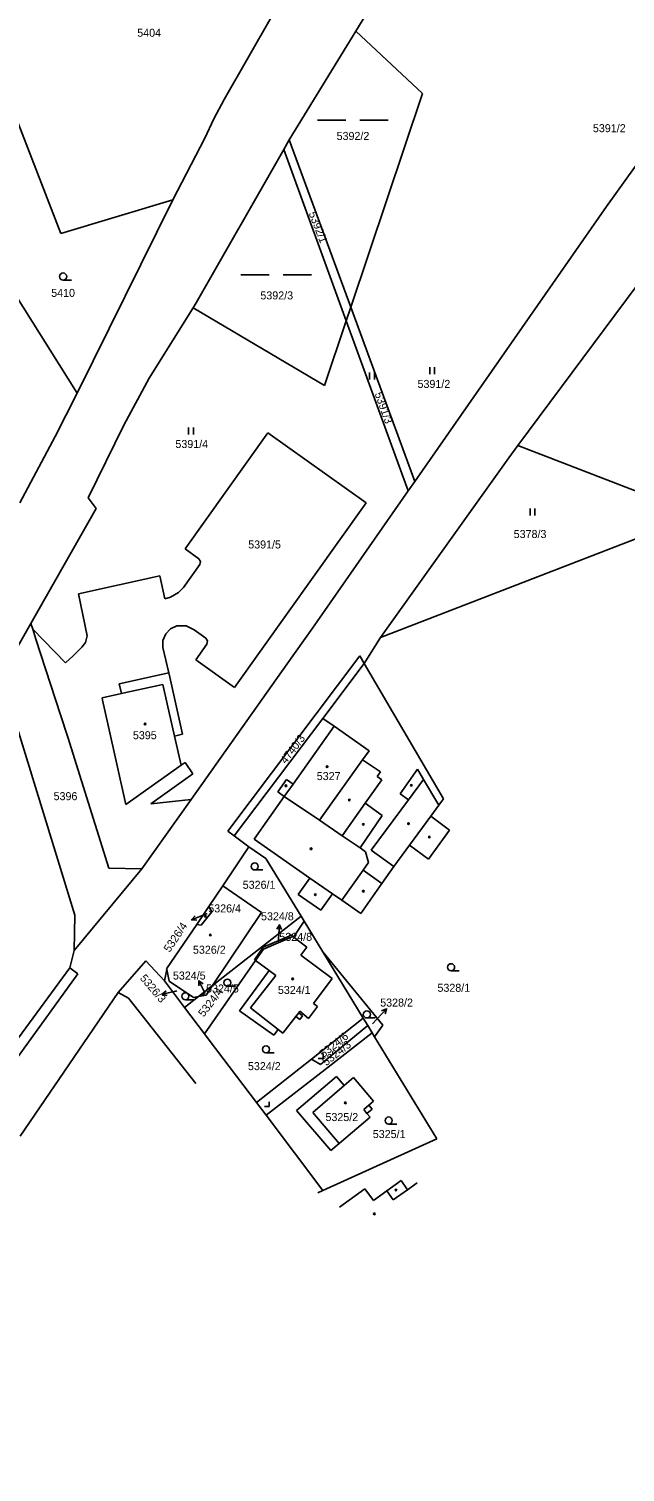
# Model space of a CAD drawing. Extents: x -717507 to -715515, y -957700 to -954941.
# Drawn here: x -716103.3 to -715976.7, y -955758.9 to -955452.3 of the extents above; entities that cross this region are included whole.
import ezdxf

# ---------------------------------------------------------------- set-up
doc = ezdxf.new("R2010")
doc.units = 0
for name, color, linetype in [('Hranice parcel', 7, 'Continuous'), ('Parcelní čísla', 7, 'Continuous'), ('Pop  PČ popisy', 7, 'Continuous'), ('Vnitřní kresba', 7, 'Continuous'), ('Značky budov', 7, 'Continuous'), ('Značky kultur', 7, 'Continuous')]:
    doc.layers.add(name, color=color, linetype=linetype)

msp = doc.modelspace()

# ---------------------------------------------------------------- linework, layer by layer
at = {"layer": 'Hranice parcel'}
for points in [[(-715980.61, -955490.06), (-715936.99, -955429.22)], [(-716033.91, -955452.78), (-716027.09, -955441.61)], [(-716061.85, -955467.33), (-716051.78, -955449.79)], [(-716048.01, -955475.9), (-716033.91, -955452.78)], [(-716033.91, -955452.78), (-716019.74, -955466.03)], [(-716064.05, -955471.46), (-716061.85, -955467.33)], [(-716034.97, -955511.43), (-716019.74, -955466.03)], [(-716106.79, -955469.23), (-716096.54, -955495.81)], [(-716065.97, -955475.56), (-716064.05, -955471.46)], [(-716072.73, -955488.62), (-716065.97, -955475.56)], [(-716049.2, -955477.98), (-716048.01, -955475.9)], [(-716048.01, -955475.9), (-716034.97, -955511.43)], [(-716067.78, -955510.54), (-716049.2, -955477.98)], [(-716049.2, -955477.98), (-716035.94, -955514.32)], [(-716096.54, -955495.81), (-716072.73, -955488.62)], [(-716093.1, -955529.72), (-716072.73, -955488.62)], [(-716021.37, -955548.49), (-715980.61, -955490.06)], [(-715999.46, -955540.82), (-715969.56, -955500.7)], [(-716106.5, -955508.39), (-716093.1, -955529.72)], [(-716068.43, -955511.57), (-716067.78, -955510.54)], [(-716077.82, -955526.49), (-716068.43, -955511.57)], [(-716068.43, -955511.57), (-716040.55, -955528.07)], [(-716035.94, -955514.32), (-716034.97, -955511.43)], [(-716034.97, -955511.43), (-716021.37, -955548.49)], [(-716040.55, -955528.07), (-716035.94, -955514.32)], [(-716035.94, -955514.32), (-716022.75, -955550.46)], [(-716083.19, -955536.49), (-716077.82, -955526.49)], [(-716097.74, -955538.89), (-716093.1, -955529.72)], [(-716090.76, -955551.92), (-716083.19, -955536.49)], [(-716070.13, -955562.79), (-716052.56, -955538.14)], [(-716052.56, -955538.14), (-716031.66, -955552.99)], [(-716105.29, -955552.97), (-716097.74, -955538.89)], [(-716001.39, -955543.41), (-715999.46, -955540.82)], [(-715999.46, -955540.82), (-715961.64, -955555.4)], [(-716028.66, -955581.62), (-716001.39, -955543.41)], [(-716042.11, -955578.21), (-716022.75, -955550.46)], [(-716022.75, -955550.46), (-716021.37, -955548.49)], [(-716090.76, -955551.92), (-716089.04, -955554.17)], [(-716031.66, -955552.99), (-716059.64, -955592.22)], [(-716102.92, -955578.62), (-716089.04, -955554.17)], [(-716028.66, -955581.62), (-715967.26, -955557.9)], [(-716067.22, -955564.87), (-716070.13, -955562.79)], [(-716070.52, -955571.02), (-716067.02, -955566.13)], [(-716066.85, -955565.46), (-716067.22, -955564.87)], [(-716067.02, -955566.13), (-716066.85, -955565.46)], [(-716092.79, -955572.36), (-716075.5, -955568.52)], [(-716075.5, -955568.52), (-716074.47, -955573.38)], [(-716073.24, -955573.07), (-716071.53, -955572.08)], [(-716071.53, -955572.08), (-716070.52, -955571.02)], [(-716090.94, -955581.22), (-716092.79, -955572.36)], [(-716074.47, -955573.38), (-716073.24, -955573.07)], [(-716043.08, -955579.59), (-716042.11, -955578.21)], [(-716109.23, -955589.72), (-716102.92, -955578.62)], [(-716102.53, -955579.81), (-716102.92, -955578.62)], [(-716102.53, -955579.81), (-716095.55, -955587.02)], [(-716101.83, -955581.98), (-716102.53, -955579.81)], [(-716091.29, -955582.68), (-716090.94, -955581.22)], [(-716074.26, -955580.84), (-716074.86, -955582.23)], [(-716073.23, -955579.76), (-716074.26, -955580.84)], [(-716071.9, -955579.14), (-716073.23, -955579.76)], [(-716069.94, -955579.11), (-716071.9, -955579.14)], [(-716068.21, -955579.99), (-716069.94, -955579.11)], [(-716065.76, -955581.72), (-716068.21, -955579.99)], [(-716048.45, -955587.22), (-716043.08, -955579.59)], [(-716101.83, -955581.98), (-716096.62, -955598)], [(-716093.95, -955585.52), (-716092.06, -955583.68)], [(-716092.06, -955583.68), (-716091.29, -955582.68)], [(-716074.86, -955582.23), (-716074.89, -955583.73)], [(-716074.89, -955583.73), (-716073.62, -955589.09)], [(-716067.9, -955586.32), (-716065.54, -955583)], [(-716065.39, -955582.31), (-716065.76, -955581.72)], [(-716065.54, -955583), (-716065.39, -955582.31)], [(-716032.08, -955587.12), (-716028.66, -955581.62)], [(-716095.55, -955587.02), (-716093.95, -955585.52)], [(-716068.85, -955615.99), (-716048.45, -955587.22)], [(-716059.64, -955592.22), (-716067.9, -955586.32)], [(-716061.05, -955622.71), (-716033.01, -955585.53)], [(-716040.92, -955598.84), (-716032.08, -955587.12)], [(-716033.01, -955585.53), (-716032.08, -955587.12)], [(-716032.08, -955587.12), (-716015.28, -955615.88)], [(-716084.16, -955591.46), (-716073.62, -955589.09)], [(-716073.62, -955589.09), (-716073.41, -955590.02)], [(-716073.41, -955590.02), (-716072.25, -955595.15)], [(-716108.34, -955592.62), (-716093.6, -955640.58)], [(-716087.79, -955594.43), (-716083.69, -955593.52)], [(-716083.69, -955593.52), (-716084.16, -955591.46)], [(-716087.68, -955594.93), (-716087.79, -955594.43)], [(-716086.57, -955599.93), (-716087.68, -955594.93)], [(-716072.25, -955595.15), (-716070.68, -955602.15)], [(-716096.62, -955598), (-716095.07, -955602.76)], [(-716059.7, -955623.74), (-716040.92, -955598.84)], [(-716040.92, -955598.84), (-716038.5, -955600.47)], [(-716095.07, -955602.76), (-716086.37, -955630.6)], [(-716082.76, -955617.05), (-716086.57, -955599.93)], [(-716070.68, -955602.15), (-716072.41, -955602.58)], [(-716072.41, -955602.58), (-716071.02, -955608.74)], [(-716047.22, -955612.76), (-716038.5, -955600.47)], [(-716071.02, -955608.74), (-716082.76, -955617.05)], [(-716071.02, -955608.74), (-716070.13, -955608.17)], [(-716070.13, -955608.17), (-716068.5, -955610.53)], [(-716068.5, -955610.53), (-716077.44, -955616.92)], [(-716050.47, -955614.38), (-716048.61, -955611.77)], [(-716048.61, -955611.77), (-716047.22, -955612.76)], [(-716050.47, -955614.38), (-716049.07, -955615.37)], [(-716079.31, -955630.74), (-716068.85, -955615.99)], [(-716077.44, -955616.92), (-716068.85, -955615.99)], [(-716055.51, -955624.44), (-716049.07, -955615.37)], [(-716017.96, -955619.55), (-716016.24, -955617.2)], [(-716016.24, -955617.2), (-716015.28, -955615.88)], [(-716017.96, -955619.55), (-716013.99, -955622.56)], [(-716059.7, -955623.74), (-716061.05, -955622.71)], [(-716059.7, -955623.74), (-716056.62, -955626.1)], [(-716018.41, -955628.66), (-716013.99, -955622.56)], [(-716062.16, -955634.37), (-716056.62, -955626.1)], [(-716056.62, -955626.1), (-716052.98, -955628.58)], [(-716055.51, -955624.44), (-716043.66, -955632.69)], [(-716025.79, -955630.27), (-716022.45, -955625.71)], [(-716022.45, -955625.71), (-716018.41, -955628.66)], [(-716052.98, -955628.58), (-716045.51, -955640.82)], [(-716028.32, -955633.85), (-716025.79, -955630.27)], [(-716093.74, -955648.11), (-716079.31, -955630.74)], [(-716086.37, -955630.6), (-716079.31, -955630.74)], [(-716046.12, -955636.22), (-716043.66, -955632.69)], [(-716065.11, -955638.74), (-716062.16, -955634.37)], [(-716062.16, -955634.37), (-716053.91, -955640.05)], [(-716046.12, -955636.22), (-716041.28, -955639.53)], [(-716041.28, -955639.53), (-716038.84, -955636.05)], [(-716038.84, -955636.05), (-716036.87, -955637.43)], [(-716032.85, -955640.23), (-716028.32, -955633.85)], [(-716067.69, -955642.55), (-716065.11, -955638.74)], [(-716065.11, -955638.74), (-716064.48, -955639.88)], [(-716036.87, -955637.43), (-716032.85, -955640.23)], [(-716093.74, -955648.11), (-716093.6, -955640.58)], [(-716074.07, -955651.99), (-716067.69, -955642.55)], [(-716067.69, -955642.55), (-716066.74, -955642.72)], [(-716066.74, -955642.72), (-716064.48, -955639.88)], [(-716064.34, -955655.54), (-716053.91, -955640.05)], [(-716064.34, -955655.54), (-716045.51, -955640.82)], [(-716046.97, -955645.01), (-716044.88, -955641.85)], [(-716045.51, -955640.82), (-716044.88, -955641.85)], [(-716044.88, -955641.85), (-716040.9, -955648.37)], [(-716053.55, -955647.39), (-716048.03, -955645.01)], [(-716047.23, -955645.12), (-716053.52, -955647.84)], [(-716048.03, -955645.01), (-716047.79, -955644.69)], [(-716047.79, -955644.69), (-716047.23, -955645.12)], [(-716046.97, -955645.01), (-716047.23, -955645.12)], [(-716047.23, -955645.12), (-716044.32, -955647.36)], [(-716094.64, -955651.79), (-716093.74, -955648.11)], [(-716055.42, -955650.07), (-716053.55, -955647.39)], [(-716053.52, -955647.84), (-716055.19, -955650.24)], [(-716044.32, -955647.36), (-716045.56, -955649.07)], [(-716040.9, -955648.37), (-716028.12, -955663.97)], [(-716040.9, -955648.37), (-716032.29, -955662.48)], [(-716133.06, -955704.12), (-716094.64, -955651.79)], [(-716084.35, -955657.02), (-716078.47, -955650.31)], [(-716078.47, -955650.31), (-716074.53, -955654.55)], [(-716074.07, -955651.99), (-716074.04, -955652.15)], [(-716055.19, -955650.24), (-716066.02, -955665.8)], [(-716055.19, -955650.24), (-716055.42, -955650.07)], [(-716052.3, -955652.37), (-716055.19, -955650.24)], [(-716045.56, -955649.07), (-716038.9, -955654.06)], [(-716074.53, -955654.55), (-716074.04, -955652.15)], [(-716074.53, -955654.55), (-716070.28, -955660.17)], [(-716074.04, -955652.15), (-716073.52, -955654.59)], [(-716073.52, -955654.59), (-716068.37, -955658.06)], [(-716058.58, -955660.88), (-716052.3, -955652.37)], [(-716042.86, -955659.34), (-716038.9, -955654.06)], [(-716105.18, -955687.56), (-716084.35, -955657.02)], [(-716084.35, -955657.02), (-716082.21, -955658.24)], [(-716070.28, -955660.17), (-716067.33, -955657.87)], [(-716068.37, -955658.06), (-716067.33, -955657.87)], [(-716067.33, -955657.87), (-716064.34, -955655.54)], [(-716067.33, -955657.87), (-716065.71, -955657.57)], [(-716065.71, -955657.57), (-716064.34, -955655.54)], [(-716082.21, -955658.24), (-716067.89, -955676.36)], [(-716070.28, -955660.17), (-716066.02, -955665.8)], [(-716058.58, -955660.88), (-716051.32, -955666.06)], [(-716046.02, -955661.32), (-716045.77, -955661.01)], [(-716045.77, -955661.01), (-716043.91, -955662.51)], [(-716043.91, -955662.51), (-716042, -955659.99)], [(-716042.86, -955659.34), (-716042, -955659.99)], [(-716049.42, -955665.65), (-716046.64, -955662.11)], [(-716046.64, -955662.11), (-716045.81, -955662.76)], [(-716046.02, -955661.32), (-716045.19, -955661.97)], [(-716045.81, -955662.76), (-716045.19, -955661.97)], [(-716043.33, -955671.19), (-716032.29, -955662.48)], [(-716031.36, -955664.01), (-716041.36, -955672.3)], [(-716032.29, -955662.48), (-716031.36, -955664.01)], [(-716031.36, -955664.01), (-716030.38, -955665.61)], [(-716029.88, -955666.44), (-716028.12, -955663.97)], [(-716066.02, -955665.8), (-716065.01, -955667.14)], [(-716065.01, -955667.14), (-716055, -955680.41)], [(-716051.32, -955666.06), (-716050.4, -955664.88)], [(-716050.4, -955664.88), (-716049.42, -955665.65)], [(-716030.38, -955665.61), (-716040.42, -955673.38)], [(-716030.38, -955665.61), (-716029.88, -955666.44)], [(-716029.88, -955666.44), (-716016.66, -955688.09)], [(-716055, -955680.41), (-716043.33, -955671.19)], [(-716040.42, -955673.38), (-716052.95, -955683.09)], [(-716041.36, -955672.3), (-716043.33, -955671.19)], [(-716046.49, -955682.05), (-716037.98, -955674.88)], [(-716037.98, -955674.88), (-716036.36, -955676.8)], [(-716036.36, -955676.8), (-716034.36, -955675.1)], [(-716034.36, -955675.1), (-716030.11, -955680.11)], [(-716055, -955680.41), (-716052.95, -955683.09)], [(-716046.49, -955682.05), (-716039.19, -955690.57)], [(-716031.51, -955682.68), (-716030.41, -955681.76)], [(-716031.1, -955680.95), (-716030.11, -955680.11)], [(-716031.1, -955680.95), (-716030.41, -955681.76)], [(-716052.95, -955683.09), (-716040.89, -955699.04)], [(-716037.44, -955689.07), (-716030.83, -955683.47)], [(-716031.51, -955682.68), (-716030.83, -955683.47)], [(-716040.89, -955699.04), (-716016.66, -955688.09)], [(-716039.19, -955690.57), (-716037.44, -955689.07)], [(-716027.31, -955699.17), (-716024.23, -955696.96)], [(-716024.23, -955696.96), (-716022.92, -955698.93)], [(-716022.92, -955698.93), (-716020.82, -955697.43)], [(-716041.98, -955699.53), (-716040.89, -955699.04)], [(-716037.34, -955702.6), (-716031.94, -955698.73)], [(-716031.94, -955698.73), (-716030.16, -955701.21)], [(-716030.16, -955701.21), (-716027.31, -955699.17)]]:
    msp.add_lwpolyline(points, dxfattribs=at)
at = {"layer": 'Pop  PČ popisy'}
for points in [[(-716065.99, -955640.43), (-716068.76, -955641.59)], [(-716067.64, -955641.67), (-716068.76, -955641.59), (-716068.03, -955640.74)], [(-716065.43, -955640.2), (-716065.99, -955640.43)], [(-716050.68, -955643.59), (-716050.13, -955642.61), (-716049.69, -955643.64)], [(-716050.29, -955645.61), (-716050.13, -955642.61)], [(-716050.32, -955646.24), (-716050.29, -955645.61)], [(-716067.23, -955655.63), (-716067.22, -955654.51), (-716066.33, -955655.19)], [(-716065.9, -955657.21), (-716067.22, -955654.51)], [(-716073.93, -955657.64), (-716075.01, -955657.38), (-716074.15, -955656.67)], [(-716072.09, -955656.71), (-716075.01, -955657.38)], [(-716071.91, -955656.67), (-716072.09, -955656.71)], [(-716029.39, -955662.68), (-716027.35, -955660.48)], [(-716028.4, -955660.87), (-716027.35, -955660.48), (-716027.66, -955661.55)], [(-716030.31, -955663.68), (-716029.39, -955662.68)]]:
    msp.add_lwpolyline(points, dxfattribs=at)
at = {"layer": 'Vnitřní kresba'}
for points in [[(-716083.41, -955593.46), (-716083.69, -955593.52)], [(-716074.89, -955591.57), (-716083.41, -955593.46)], [(-716073.95, -955595.72), (-716074.89, -955591.57)], [(-716072.41, -955602.58), (-716073.95, -955595.72)], [(-716038.5, -955600.47), (-716031.07, -955605.68)], [(-716032.47, -955607.62), (-716031.07, -955605.68)], [(-716041.63, -955620.43), (-716032.47, -955607.62)], [(-716032.47, -955607.62), (-716028.67, -955610.16)], [(-716031.89, -955616.81), (-716028.36, -955611.86)], [(-716029.37, -955611.14), (-716028.67, -955610.16)], [(-716029.37, -955611.14), (-716028.36, -955611.86)], [(-716024.44, -955614.81), (-716020.79, -955609.56)], [(-716022.71, -955616.09), (-716019.49, -955611.74)], [(-716020.79, -955609.56), (-716019.49, -955611.74)], [(-716019.49, -955611.74), (-716016.24, -955617.2)], [(-716049.07, -955615.37), (-716047.22, -955612.76)], [(-716024.44, -955614.81), (-716022.71, -955616.09)], [(-716049.07, -955615.37), (-716041.63, -955620.43)], [(-716036.81, -955623.7), (-716031.89, -955616.81)], [(-716031.89, -955616.81), (-716028.28, -955619.38)], [(-716030.65, -955626.8), (-716022.71, -955616.09)], [(-716041.63, -955620.43), (-716036.81, -955623.7)], [(-716032.99, -955626.3), (-716028.28, -955619.38)], [(-716022.45, -955625.71), (-716017.96, -955619.55)], [(-716036.81, -955623.7), (-716032.99, -955626.3)], [(-716032.99, -955626.3), (-716031.83, -955627.15)], [(-716031.83, -955627.15), (-716031.17, -955629.38)], [(-716030.65, -955626.8), (-716025.79, -955630.27)], [(-716032.34, -955631.03), (-716031.17, -955629.38)], [(-716043.66, -955632.69), (-716038.84, -955636.05)], [(-716036.87, -955637.43), (-716032.34, -955631.03)], [(-716032.34, -955631.03), (-716028.32, -955633.85)], [(-716094.64, -955651.79), (-716092.97, -955653.02)], [(-716169.42, -955758.89), (-716092.97, -955653.02)], [(-716056.24, -955660.27), (-716050.85, -955653.43)], [(-716052.3, -955652.37), (-716050.85, -955653.43)], [(-716056.24, -955660.27), (-716050.4, -955664.88)], [(-716046.64, -955662.11), (-716046.02, -955661.32)], [(-716043.04, -955682.47), (-716036.36, -955676.8)], [(-716043.04, -955682.47), (-716037.44, -955689.07)], [(-716032.19, -955681.87), (-716031.1, -955680.95)], [(-716032.19, -955681.87), (-716031.51, -955682.68)], [(-716027.31, -955699.17), (-716025.95, -955701.08)], [(-716025.95, -955701.08), (-716022.92, -955698.93)]]:
    msp.add_lwpolyline(points, dxfattribs=at)
at = {"layer": 'Značky budov'}
for centre in [(-716078.65, -955599.97), (-716039.98, -955609.03), (-716048.74, -955613.1), (-716022.1, -955613.02), (-716035.25, -955616.13), (-716032.3, -955621.3), (-716022.69, -955621.15), (-716018.26, -955623.97), (-716043.38, -955626.48), (-716042.49, -955636.24), (-716032.3, -955635.5), (-716065.87, -955640.85), (-716064.79, -955644.79), (-716047.29, -955654.11), (-716066.27, -955657.39), (-716036.11, -955680.46), (-716025.34, -955698.97), (-716029.96, -955704.03)]:
    msp.add_circle(centre, 0.175, dxfattribs=at)
at = {"layer": 'Značky kultur'}
for points in [[(-716042.03, -955471.7), (-716036.03, -955471.7)], [(-716033.03, -955471.7), (-716027.03, -955471.7)], [(-716058.3, -955504.57), (-716052.3, -955504.57)], [(-716049.3, -955504.57), (-716043.3, -955504.57)], [(-716096.06, -955505.68), (-716094.31, -955505.68)], [(-716030.97, -955526.83), (-716030.97, -955525.33)], [(-716029.93, -955526.83), (-716029.93, -955525.33)], [(-716018.19, -955525.68), (-716018.19, -955524.18)], [(-716017.15, -955525.68), (-716017.15, -955524.18)], [(-716069.41, -955538.51), (-716069.41, -955537.01)], [(-716068.37, -955538.51), (-716068.37, -955537.01)], [(-715996.86, -955555.67), (-715996.86, -955554.17)], [(-715995.82, -955555.67), (-715995.82, -955554.17)], [(-716055.36, -955630.99), (-716053.61, -955630.99)], [(-716013.64, -955652.39), (-716011.89, -955652.39)], [(-716061.17, -955655.68), (-716059.42, -955655.68)], [(-716070.09, -955658.55), (-716068.34, -955658.55)], [(-716031.54, -955662.42), (-716029.79, -955662.42)], [(-716052.96, -955669.84), (-716051.21, -955669.84)], [(-716041.85, -955671), (-716040.85, -955671), (-716040.85, -955670)], [(-716053.31, -955681.21), (-716052.31, -955681.21), (-716052.31, -955680.21)], [(-716026.91, -955684.95), (-716025.16, -955684.95)]]:
    msp.add_lwpolyline(points, dxfattribs=at)
for centre, radius in [((-716096.06, -955504.93), 0.75), ((-716055.36, -955630.24), 0.75), ((-716049.17, -955645.72), 0.175), ((-716013.64, -955651.64), 0.75), ((-716061.17, -955654.93), 0.75), ((-716070.09, -955657.8), 0.75), ((-716031.54, -955661.67), 0.75), ((-716052.96, -955669.09), 0.75), ((-716026.91, -955684.2), 0.75)]:
    msp.add_circle(centre, radius, dxfattribs=at)

# ---------------------------------------------------------------- texts
at = {"layer": 'Parcelní čísla'}
for s, p in [('5404', (-716080.32, -955454)), ('5392/2', (-716037.96, -955475.92)), ('5391/2', (-715983.51, -955474.27)), ('5410', (-716098.6, -955509.25)), ('5392/3', (-716054.16, -955509.79)), ('5391/2', (-716020.77, -955528.59)), ('5391/4', (-716072.21, -955541.35)), ('5378/3', (-716000.34, -955560.48)), ('5391/5', (-716056.74, -955562.69)), ('5395', (-716081.24, -955603.21)), ('5327', (-716042.18, -955611.89)), ('5396', (-716098.09, -955616.16)), ('5326/1', (-716057.91, -955634.98)), ('5326/4', (-716065.23, -955640)), ('5324/8', (-716054.02, -955641.67)), ('5324/8', (-716050.12, -955646.04)), ('5326/2', (-716068.48, -955648.78)), ('5324/5', (-716072.74, -955654.26)), ('5328/1', (-716016.54, -955656.86)), ('5324/5', (-716065.7, -955657.01)), ('5324/1', (-716050.44, -955657.32)), ('5328/2', (-716028.7, -955660)), ('5324/2', (-716056.8, -955673.5)), ('5325/2', (-716040.33, -955684.32)), ('5325/1', (-716030.28, -955687.93))]:
    msp.add_text(s, height=1.7, dxfattribs=at).set_placement(p)
for s, rotation, p in [('5392/1', 291.2023, (-716043.94, -955491.51)), ('5391/3', 289.5023, (-716029.91, -955529.81)), ('4740/3', 52.9004, (-716048.73, -955608.58)), ('5326/4', 56.1004, (-716073.44, -955648.62)), ('5326/3', 310.4025, (-716079.86, -955654.05)), ('5324/4', 52.4004, (-716066.19, -955662.34)), ('5324/6', 38.2003, (-716040.75, -955670.93)), ('5324/3', 38.3003, (-716040.16, -955672.7))]:
    msp.add_text(s, height=1.7, rotation=rotation, dxfattribs=at).set_placement(p)

doc.saveas('drawing.dxf')
